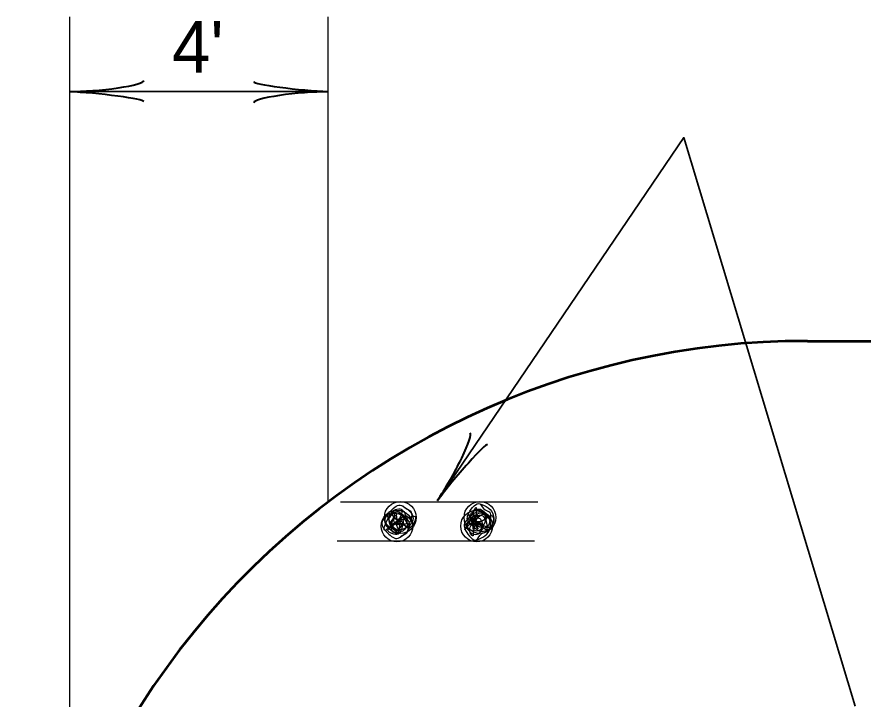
# Model space of a CAD drawing. Extents: x -133 to 547, y -328 to 112.
# Drawn here: x 391.28 to 424.07, y -59.17 to -32.75 of the extents above; entities that cross this region are included whole.
import ezdxf

# ---------------------------------------------------------------- set-up
doc = ezdxf.new("R2010")
doc.units = 0
doc.header["$LTSCALE"] = 0.8
doc.layers.add('1', color=7, linetype='Continuous', lineweight=35)
doc.layers.add('4', color=7, linetype='Continuous', lineweight=25)

msp = doc.modelspace()

# ---------------------------------------------------------------- linework, layer by layer
at = {"layer": '1', "lineweight": 25}
for p, q in [((393.3207, -32.7518), (393.3207, -64.8886)), ((403.3381, -32.7518), (403.3381, -51.5408)), ((411.4683, -51.5485), (403.8183, -51.5485)), ((411.3402, -53.0608), (403.6903, -53.0608))]:
    msp.add_line(p, q, dxfattribs=at)
at = {"layer": '1'}
msp.add_line((403.3381, -35.646), (393.3207, -35.646), dxfattribs=at)
at = {"layer": '1', "lineweight": 53}
msp.add_line((421.922, -45.3032), (468.5003, -45.3032), dxfattribs=at)
at = {"layer": '1'}
msp.add_lwpolyline([(407.5847, -51.4791), (417.1258, -37.4246), (423.7735, -59.452)], dxfattribs=at)
at = {"layer": '1', "lineweight": 53}
msp.add_arc((421.8392, -75.8587), 30.5557, 89.84467, 191.96498, dxfattribs=at)
at = {"layer": '1', "lineweight": 40}
for centre, major_axis, ratio, start_param, end_param in [((394.4119, -35.3697), (-1.7857, -0.1562), 0.122415, 0.8963533, 3.1415927), ((402.2176, -35.4344), (1.7565, -0.1757), 0.07063, 3.1407148, 5.41811), ((394.4412, -35.8576), (-1.7565, 0.1757), 0.07063, 3.1407148, 5.41811), ((402.2469, -35.9223), (1.7857, 0.1562), 0.122415, 0.8963533, 3.1415927), ((407.969, -50.4211), (-0.8738, -1.5651), 0.122415, 0.8963533, 3.1415927), ((407.969, -50.4211), (-0.8738, -1.5651), 0.122415, 0.8963533, 3.1415927), ((408.3891, -50.6709), (1.1319, 1.3546), 0.07063, 6.2823074, 8.5597026), ((408.3891, -50.6709), (1.1319, 1.3546), 0.07063, 6.2823074, 8.5597026)]:
    msp.add_ellipse(centre, major_axis=major_axis, ratio=ratio, start_param=start_param, end_param=end_param, dxfattribs=at)
at = {"layer": '1', "lineweight": 25}
for points in [[(406.0602, -52.9409), (406.3603, -52.7309), (406.5103, -52.4309), (406.4203, -52.2208), (406.0902, -52.0108), (405.7602, -52.0108), (405.4303, -52.3408), (405.6403, -52.7308), (406.0602, -52.9409), (406.2403, -52.8208), (406.3902, -52.7309), (406.4503, -52.4608), (406.2403, -52.1009), (406.1203, -51.9509), (405.7003, -52.1908), (405.7602, -52.4909), (405.8202, -52.6708), (405.9403, -52.7309), (406.1202, -52.7309), (406.2102, -52.5508), (406.2403, -52.2209), (406.0302, -52.2209), (405.8803, -52.1909), (405.7602, -52.3709), (405.9703, -52.6409), (406.1503, -52.5208), (406.1803, -52.4008), (405.9703, -52.3709), (406.0003, -52.3108), (405.5503, -52.6408), (405.9403, -51.9209), (406.0302, -52.3408), (406.3003, -52.0708), (406.6003, -52.4909), (405.9703, -52.3709), (406.0902, -52.7609), (405.6703, -52.6709), (405.9703, -52.3709)], [(406.1882, -51.6684), (406.4883, -51.8784), (406.6383, -52.1784), (406.5483, -52.3885), (406.2183, -52.5985), (405.8882, -52.5985), (405.5583, -52.2685), (405.7683, -51.8785), (406.1882, -51.6684), (406.3683, -51.7885), (406.5182, -51.8784), (406.5783, -52.1485), (406.3683, -52.5084), (406.2483, -52.6584), (405.8283, -52.4185), (405.8882, -52.1184), (405.9482, -51.9385), (406.0683, -51.8784), (406.2482, -51.8784), (406.3382, -52.0585), (406.3683, -52.3884), (406.1583, -52.3884), (406.0083, -52.4184), (405.8882, -52.2384), (406.0983, -51.9684), (406.2783, -52.0885), (406.3083, -52.2085), (406.0983, -52.2384), (406.1283, -52.2985), (405.6783, -51.9685), (406.0683, -52.6884), (406.1583, -52.2685), (406.4282, -52.5385), (406.7283, -52.1184), (406.0983, -52.2384), (406.2183, -51.8484), (405.7983, -51.9384), (406.0983, -52.2384)], [(409.2183, -51.6085), (409.5483, -51.7585), (409.7583, -52.0885), (409.6983, -52.4484), (409.3082, -52.6884), (408.9483, -52.4785), (408.7382, -52.1784), (408.7983, -51.9685), (409.2183, -51.6085), (409.4283, -51.8484), (409.6083, -51.9384), (409.6383, -52.1184), (409.4283, -52.5385), (409.2183, -52.5084), (409.0682, -52.3884), (408.8282, -52.2385), (409.0082, -51.8785), (409.2482, -51.8185), (409.3983, -51.9384), (409.4882, -52.1184), (409.4282, -52.2985), (409.3683, -52.4185), (409.0682, -52.3285), (409.1283, -52.1185), (409.1282, -51.9985), (409.3683, -51.9985), (409.4283, -52.1784), (409.0983, -52.2985), (409.0383, -52.2685), (408.7683, -51.9985), (409.1583, -52.5685), (409.0683, -52.2985), (409.5183, -52.5985), (409.7283, -52.0885), (409.0983, -52.2985), (409.0683, -51.7585), (408.9783, -51.8784), (409.0983, -52.2985)], [(409.0902, -53.0008), (409.4203, -52.8508), (409.6303, -52.5208), (409.5703, -52.1609), (409.1803, -51.9209), (408.8203, -52.1308), (408.6103, -52.4309), (408.6703, -52.6408), (409.0902, -53.0008), (409.3003, -52.7609), (409.4803, -52.6709), (409.5103, -52.4909), (409.3003, -52.0708), (409.0902, -52.1009), (408.9402, -52.2209), (408.7002, -52.3708), (408.8802, -52.7308), (409.1202, -52.7908), (409.2703, -52.6709), (409.3603, -52.4909), (409.3003, -52.3108), (409.2403, -52.1908), (408.9402, -52.2808), (409.0003, -52.4908), (409.0002, -52.6108), (409.2403, -52.6108), (409.3003, -52.4309), (408.9702, -52.3108), (408.9103, -52.3408), (408.6403, -52.6108), (409.0302, -52.0408), (408.9403, -52.3108), (409.3903, -52.0108), (409.6003, -52.5208), (408.9702, -52.3108), (408.9403, -52.8508), (408.8502, -52.7309), (408.9702, -52.3108)]]:
    msp.add_spline(points, degree=3, dxfattribs=at)
at = {"layer": '4'}
for centre in [(406.1401, -52.1389), (409.2253, -52.1386), (406.0121, -52.4705), (409.0973, -52.4707)]:
    msp.add_circle(centre, 0.615, dxfattribs=at)

# ---------------------------------------------------------------- texts
at = {"layer": '1'}
msp.add_text("4'", height=2, dxfattribs=at).set_placement((397.2953, -34.909))

doc.saveas('drawing.dxf')
